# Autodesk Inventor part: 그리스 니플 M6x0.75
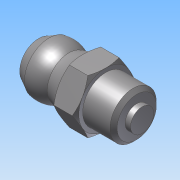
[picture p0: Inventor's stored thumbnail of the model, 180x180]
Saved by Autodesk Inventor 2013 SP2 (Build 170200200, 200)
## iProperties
Created: 2025-10
Part Number: 그리스 니플 M6x0.75
Material: Generic
Document SubType Name: Modeling
Designer: a
Density: 1 g/cm^3
Author: a
변환 표준: STEP AP214IS
전처리기: Build: 200, Release: 2013 SP2 Update 6 - Date: Thu 07/17/2014
전송 단위: 밀리미터
불확실성: 0.01
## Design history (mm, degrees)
node "그리스 니플 M6x0.751"
body "Solid1"
node "기준1"
